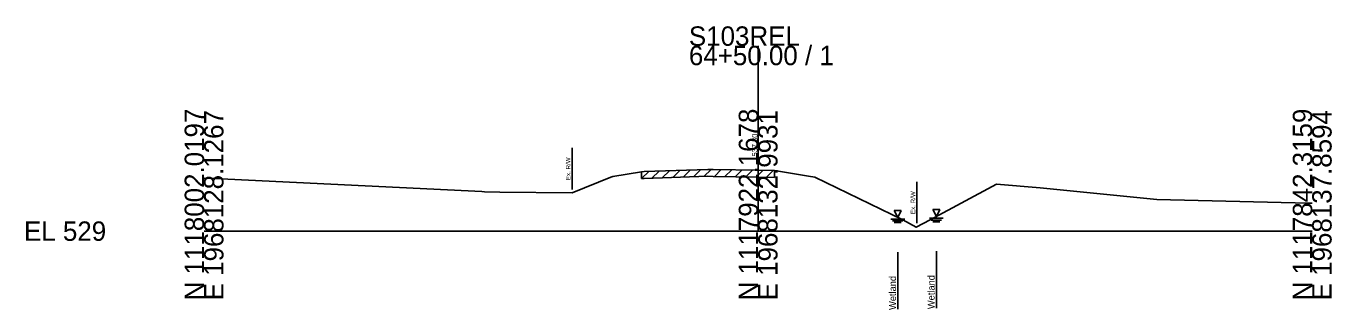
# Model space of a CAD drawing. Extents: x -26 to 163, y -10 to 24518.
# Drawn here: x -25.7 to 162.8, y 12988.6 to 13029.6 of the extents above; entities that cross this region are included whole.
import ezdxf

# ---------------------------------------------------------------- set-up
doc = ezdxf.new("R2010")
doc.units = 0
for name, color, linetype in [('RD_GPK_XS_Cell', 7, 'Continuous'), ('RD_XS_ExGround', 7, 'Continuous'), ('RD_XS_ExPaveRet', 7, 'Continuous'), ('RD_XS_ExRW', 7, 'Continuous'), ('RD_XS_EXWetland', 7, 'Continuous'), ('RD_XS_TX_Elev_EX', 7, 'Continuous')]:
    doc.layers.add(name, color=color, linetype=linetype)

msp = doc.modelspace()

# ---------------------------------------------------------------- linework, layer by layer
at = {"layer": 'RD_GPK_XS_Cell'}
for p, q in [((80, 13000), (80, 13026.77)), ((0, 13000), (80, 13000)), ((80, 13000), (160, 13000))]:
    msp.add_line(p, q, dxfattribs=at)
at = {"layer": 'RD_XS_ExGround'}
msp.add_lwpolyline([(0, 13007.67), (1.44, 13007.62), (40.09, 13005.7), (40.49, 13005.68), (42.7, 13005.65), (53.13, 13005.51), (58.72, 13007.79), (59.02, 13007.91), (63.15, 13008.58), (63.55, 13008.6), (72.74, 13008.92), (73.51, 13008.91), (80, 13008.8), (82.34, 13008.76), (87.27, 13007.95), (88.2, 13007.79), (100.88, 13001.62), (102.82, 13000.57), (104.85, 13001.62), (114.4, 13006.8), (120.72, 13006.24), (137.57, 13004.57), (159.5, 13004.04), (160, 13004.03)], dxfattribs=at)
at = {"layer": 'RD_XS_ExPaveRet'}
for p, q in [((67.67, 13007.74), (68.71, 13008.78)), ((69.17, 13007.8), (70.21, 13008.83)), ((70.68, 13007.85), (71.72, 13008.89)), ((72.18, 13007.9), (73.2, 13008.92)), ((73.69, 13007.91), (74.67, 13008.89)), ((75.19, 13007.88), (76.18, 13008.87)), ((76.69, 13007.86), (77.68, 13008.84)), ((78.2, 13007.83), (79.18, 13008.81)), ((79.7, 13007.8), (80.69, 13008.78)), ((81.21, 13007.78), (82.19, 13008.76)), ((82.34, 13008.76), (82.34, 13007.76)), ((63.15, 13007.58), (64.2, 13008.62)), ((63.15, 13007.58), (63.15, 13008.58)), ((63.15, 13007.58), (63.55, 13007.6)), ((63.55, 13007.6), (72.74, 13007.92)), ((64.66, 13007.63), (65.7, 13008.67)), ((66.16, 13007.69), (67.2, 13008.73)), ((72.74, 13007.92), (73.51, 13007.91)), ((73.51, 13007.91), (80, 13007.8)), ((80, 13007.8), (82.34, 13007.76))]:
    msp.add_line(p, q, dxfattribs=at)
at = {"layer": 'RD_XS_ExRW'}
for p, q in [((53.14, 13012.02), (53.14, 13006.02)), ((53.14, 13012.01), (53.14, 13006.01)), ((102.93, 13007.13), (102.93, 13001.13))]:
    msp.add_line(p, q, dxfattribs=at)
at = {"layer": 'RD_XS_EXWetland'}
for p, q in [((105.23, 13003.1), (105.73, 13002.1)), ((106.23, 13003.1), (105.23, 13003.1)), ((105.23, 13003.1), (105.73, 13002.1)), ((106.23, 13003.1), (105.23, 13003.1)), ((105.73, 13002.1), (106.23, 13003.1)), ((105.73, 13002.1), (106.23, 13003.1)), ((99.16, 13001.73), (101.16, 13001.73)), ((99.16, 13001.73), (101.16, 13001.73)), ((99.41, 13001.48), (100.91, 13001.48)), ((99.41, 13001.48), (100.91, 13001.48)), ((99.66, 13002.98), (100.16, 13001.98)), ((100.66, 13002.98), (99.66, 13002.98)), ((99.66, 13002.98), (100.16, 13001.98)), ((100.66, 13002.98), (99.66, 13002.98)), ((99.66, 13001.23), (100.66, 13001.23)), ((99.66, 13001.23), (100.66, 13001.23)), ((100.16, 13001.98), (100.66, 13002.98)), ((100.16, 13001.98), (100.66, 13002.98)), ((104.73, 13001.85), (106.73, 13001.85)), ((104.73, 13001.85), (106.73, 13001.85)), ((104.98, 13001.6), (106.48, 13001.6)), ((104.98, 13001.6), (106.48, 13001.6)), ((105.23, 13001.35), (106.23, 13001.35)), ((105.23, 13001.35), (106.23, 13001.35)), ((100.16, 12996.98), (100.16, 12988.73)), ((100.16, 12996.98), (100.16, 12988.73)), ((105.73, 12997.1), (105.73, 12988.85)), ((105.73, 12997.1), (105.73, 12988.85))]:
    msp.add_line(p, q, dxfattribs=at)

# ---------------------------------------------------------------- texts
at = {"layer": 'RD_GPK_XS_Cell'}
for s, p in [('S103REL', (70, 13026.77)), ('64+50.00 / 1', (70, 13023.97)), ('EL 529', (-26, 12998.6))]:
    msp.add_text(s, height=2.8, dxfattribs=at).set_placement(p)
for s, p in [('N 1118002.0197', (0, 12990)), ('E 1968128.1267', (2.8, 12990)), ('N 1117922.1678', (80, 12990)), ('E 1968132.9931', (82.8, 12990)), ('N 1117842.3159', (160, 12990)), ('E 1968137.8594', (162.8, 12990))]:
    msp.add_text(s, height=2.8, rotation=90, dxfattribs=at).set_placement(p)
at = {"layer": 'RD_XS_ExRW'}
for p in [(52.89, 13007.36), (52.89, 13007.36), (102.68, 13002.47)]:
    msp.add_text('Ex. R/W ', height=0.65, rotation=90, dxfattribs=at).set_placement(p)
at = {"layer": 'RD_XS_EXWetland'}
for p in [(99.91, 12988.62), (99.91, 12988.62), (105.48, 12988.74), (105.48, 12988.74)]:
    msp.add_text('Wetland ', height=1, rotation=90, dxfattribs=at).set_placement(p)
at = {"layer": 'RD_XS_TX_Elev_EX'}
msp.add_text('537.80', height=0.8, rotation=90, dxfattribs=at).set_placement((79.9, 13010.8))

doc.saveas('drawing.dxf')
